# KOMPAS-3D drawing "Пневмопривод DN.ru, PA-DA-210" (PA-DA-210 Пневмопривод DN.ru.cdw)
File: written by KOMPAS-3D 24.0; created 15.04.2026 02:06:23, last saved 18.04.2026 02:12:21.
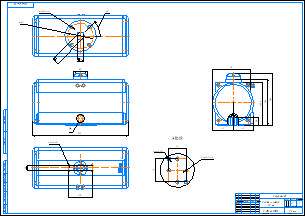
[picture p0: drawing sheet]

Document properties: Автор: DN.ru; Форматы листов документа: A1; Полное имя файла: PA-DA-210 Пневмопривод DN.ru.m3d; Масса: 47; Наименование: Пневмопривод DN.ru; Количество листов документа: 1; Примечание: D290-00300

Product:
- Part/product: Пневмопривод DN.ru  | designation PA-DA-210
    Масса: 47
    Раздел спецификации: Прочие изделия
    Примечание: D290-00300

Views: Вид 1, Вид:1, Проекционный вид 2, Проекционный вид 5, Местный разрез 1, Выносной элемент 6, Выносной элемент А, Выносной элемент
Referenced files in C:\Работа\PA-DA-х Пневмопривод DN.ru\052\: PA-DA-052 Пневмопривод DN.ru.m3d
Referenced files in C:\Работа\PA-DA-х Пневмопривод DN.ru\210\: PA-DA-210 Пневмопривод DN.ru.m3d
Referenced files in C:\Работа\PA-DA-х Пневмопривод DN.ru\160\: PA-DA-160 Пневмопривод DN.ru.m3d
Referenced files in C:\Program Files\ASCON\KOMPAS-3D v24\Templates\: Чертеж_DN.ru.cdt
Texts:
  objid
  viewid
  PA-DA-210
  Чертеж_DN.ru.cdt
  Пневмопривод
  Пневмопривод DN.ru
  PA-DA-210 Пневмопривод DN.ru
Dimensions and other numbers on the sheet: 0; 3; 2; 4; 80; 608; 532; 36; 140; 4 отв.; 16; 6; 210; 113; 235,5; 255; 285; 40; 7; 1; 2 отв.; 24; 32; 5; 1:2; 47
